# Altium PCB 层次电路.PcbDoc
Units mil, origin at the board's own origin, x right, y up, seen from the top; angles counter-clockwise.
Board outline 3000 x 3000 mil, 4 copper layers (Top Layer, VCC, GND, Bottom Layer), stack 30.634 mil thick; 34 components, 49 nets, 170 pads, 0 vias.
Unrouted connection lines stored in the file: 119.
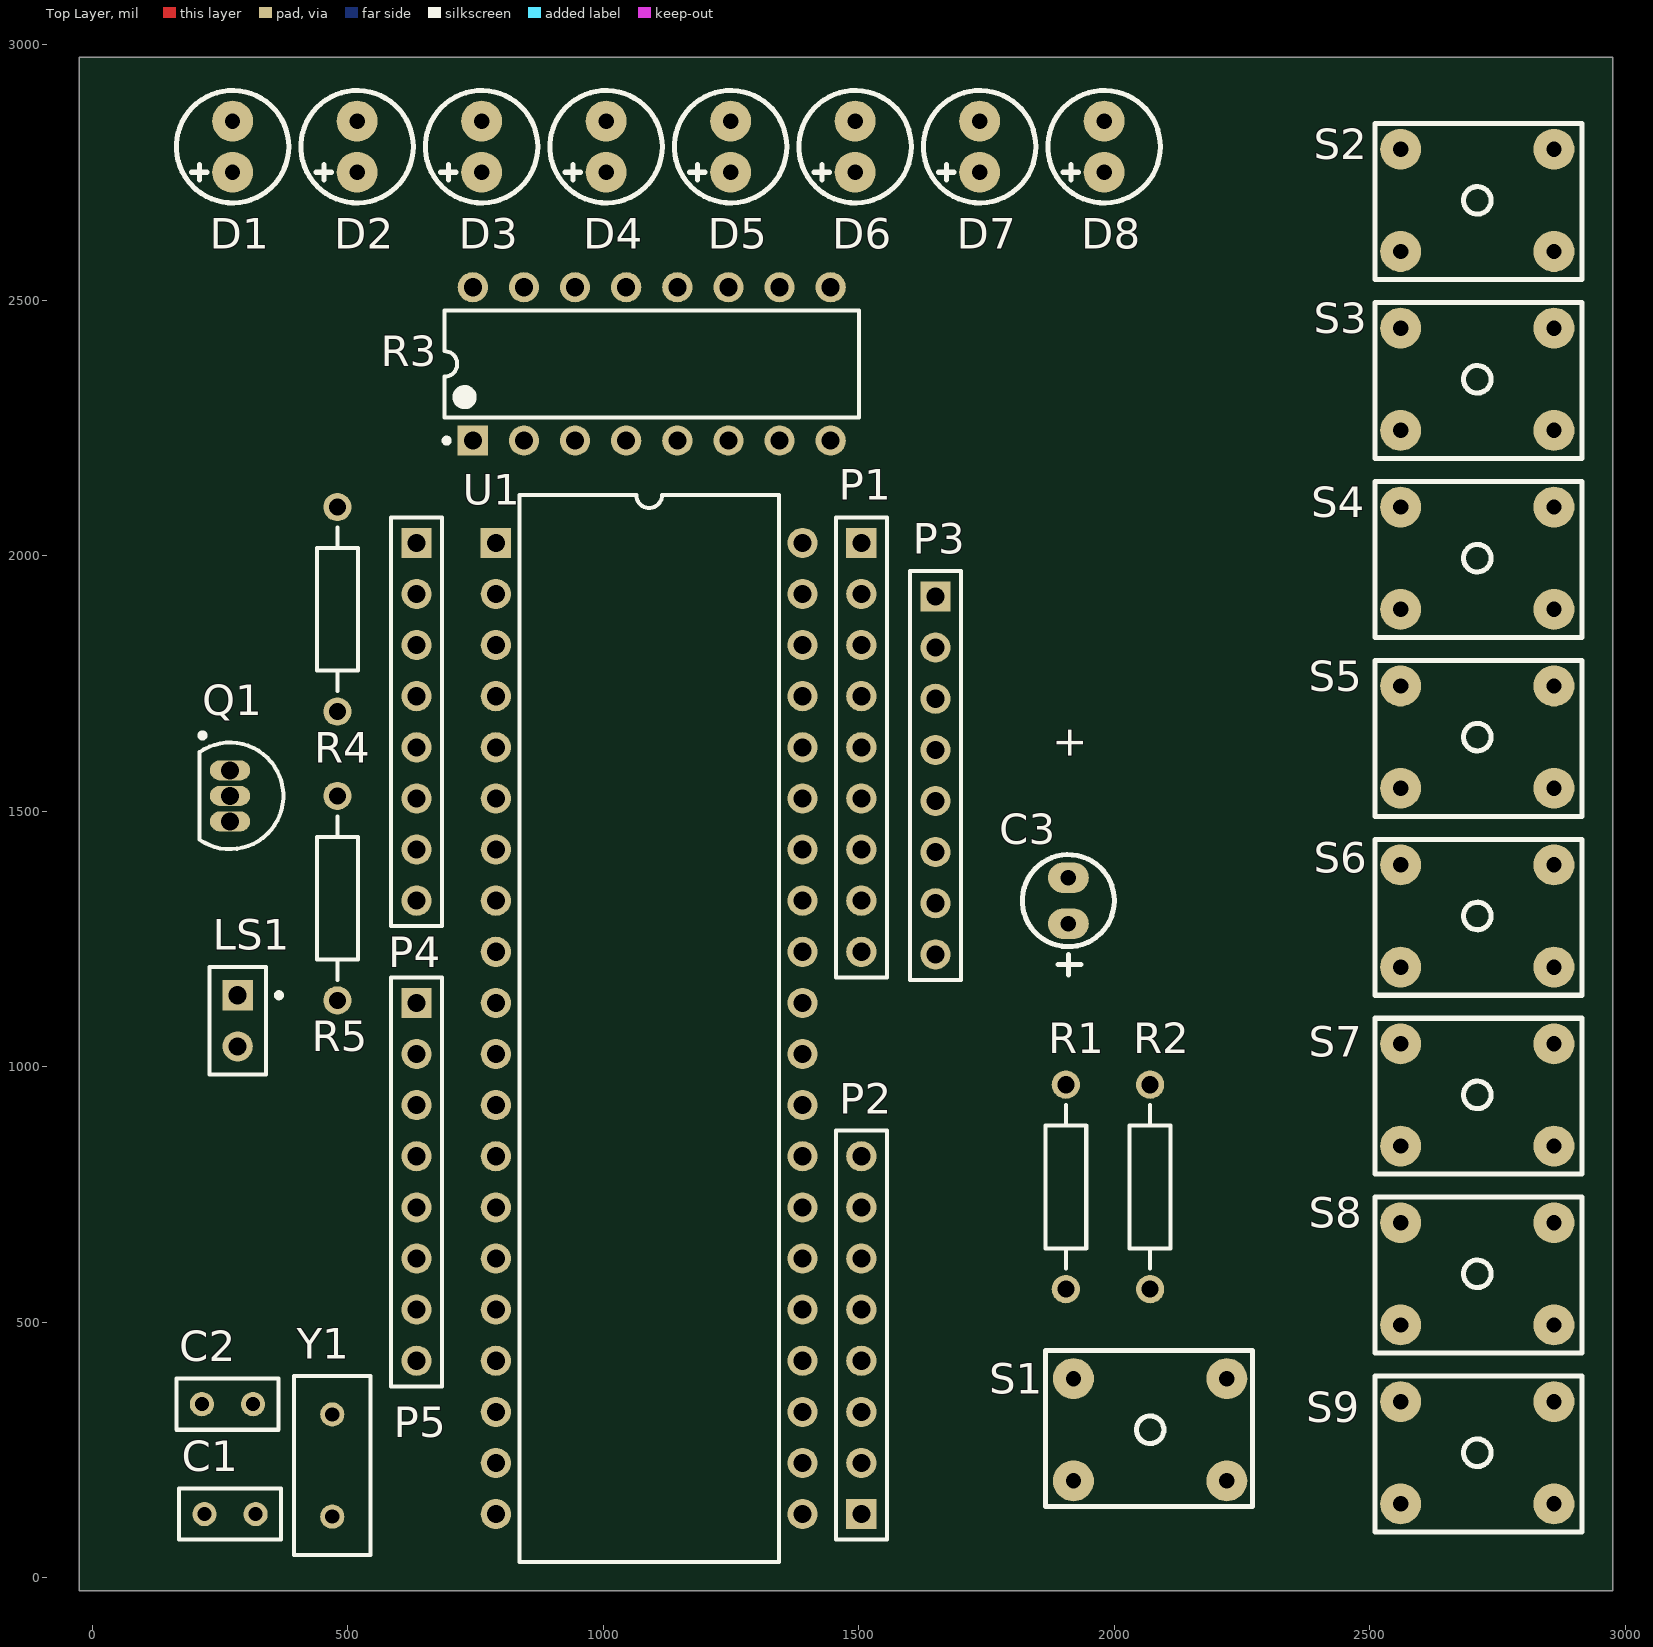
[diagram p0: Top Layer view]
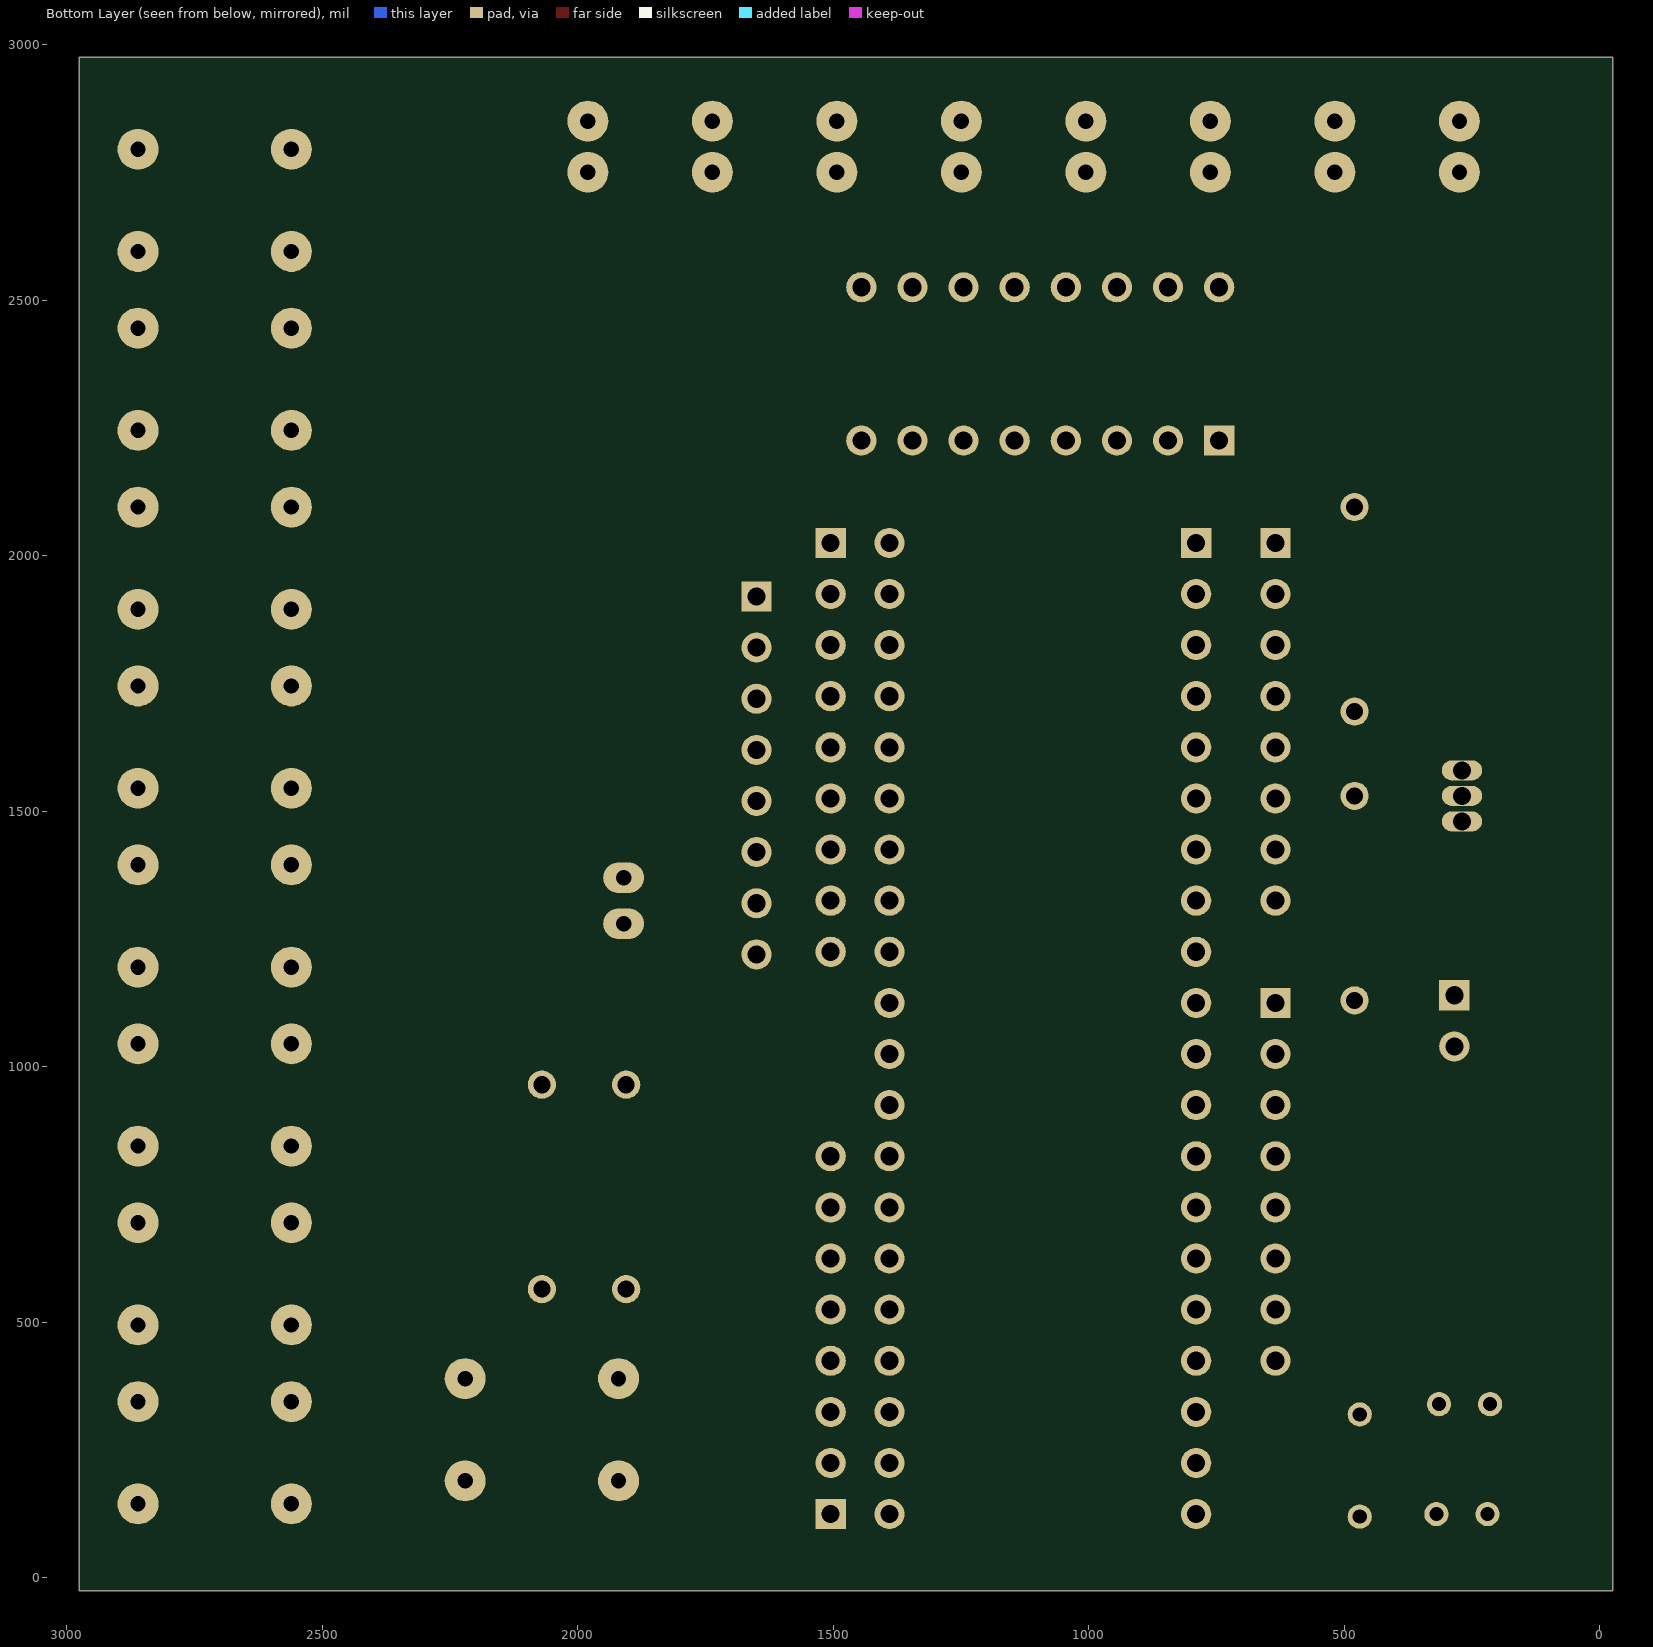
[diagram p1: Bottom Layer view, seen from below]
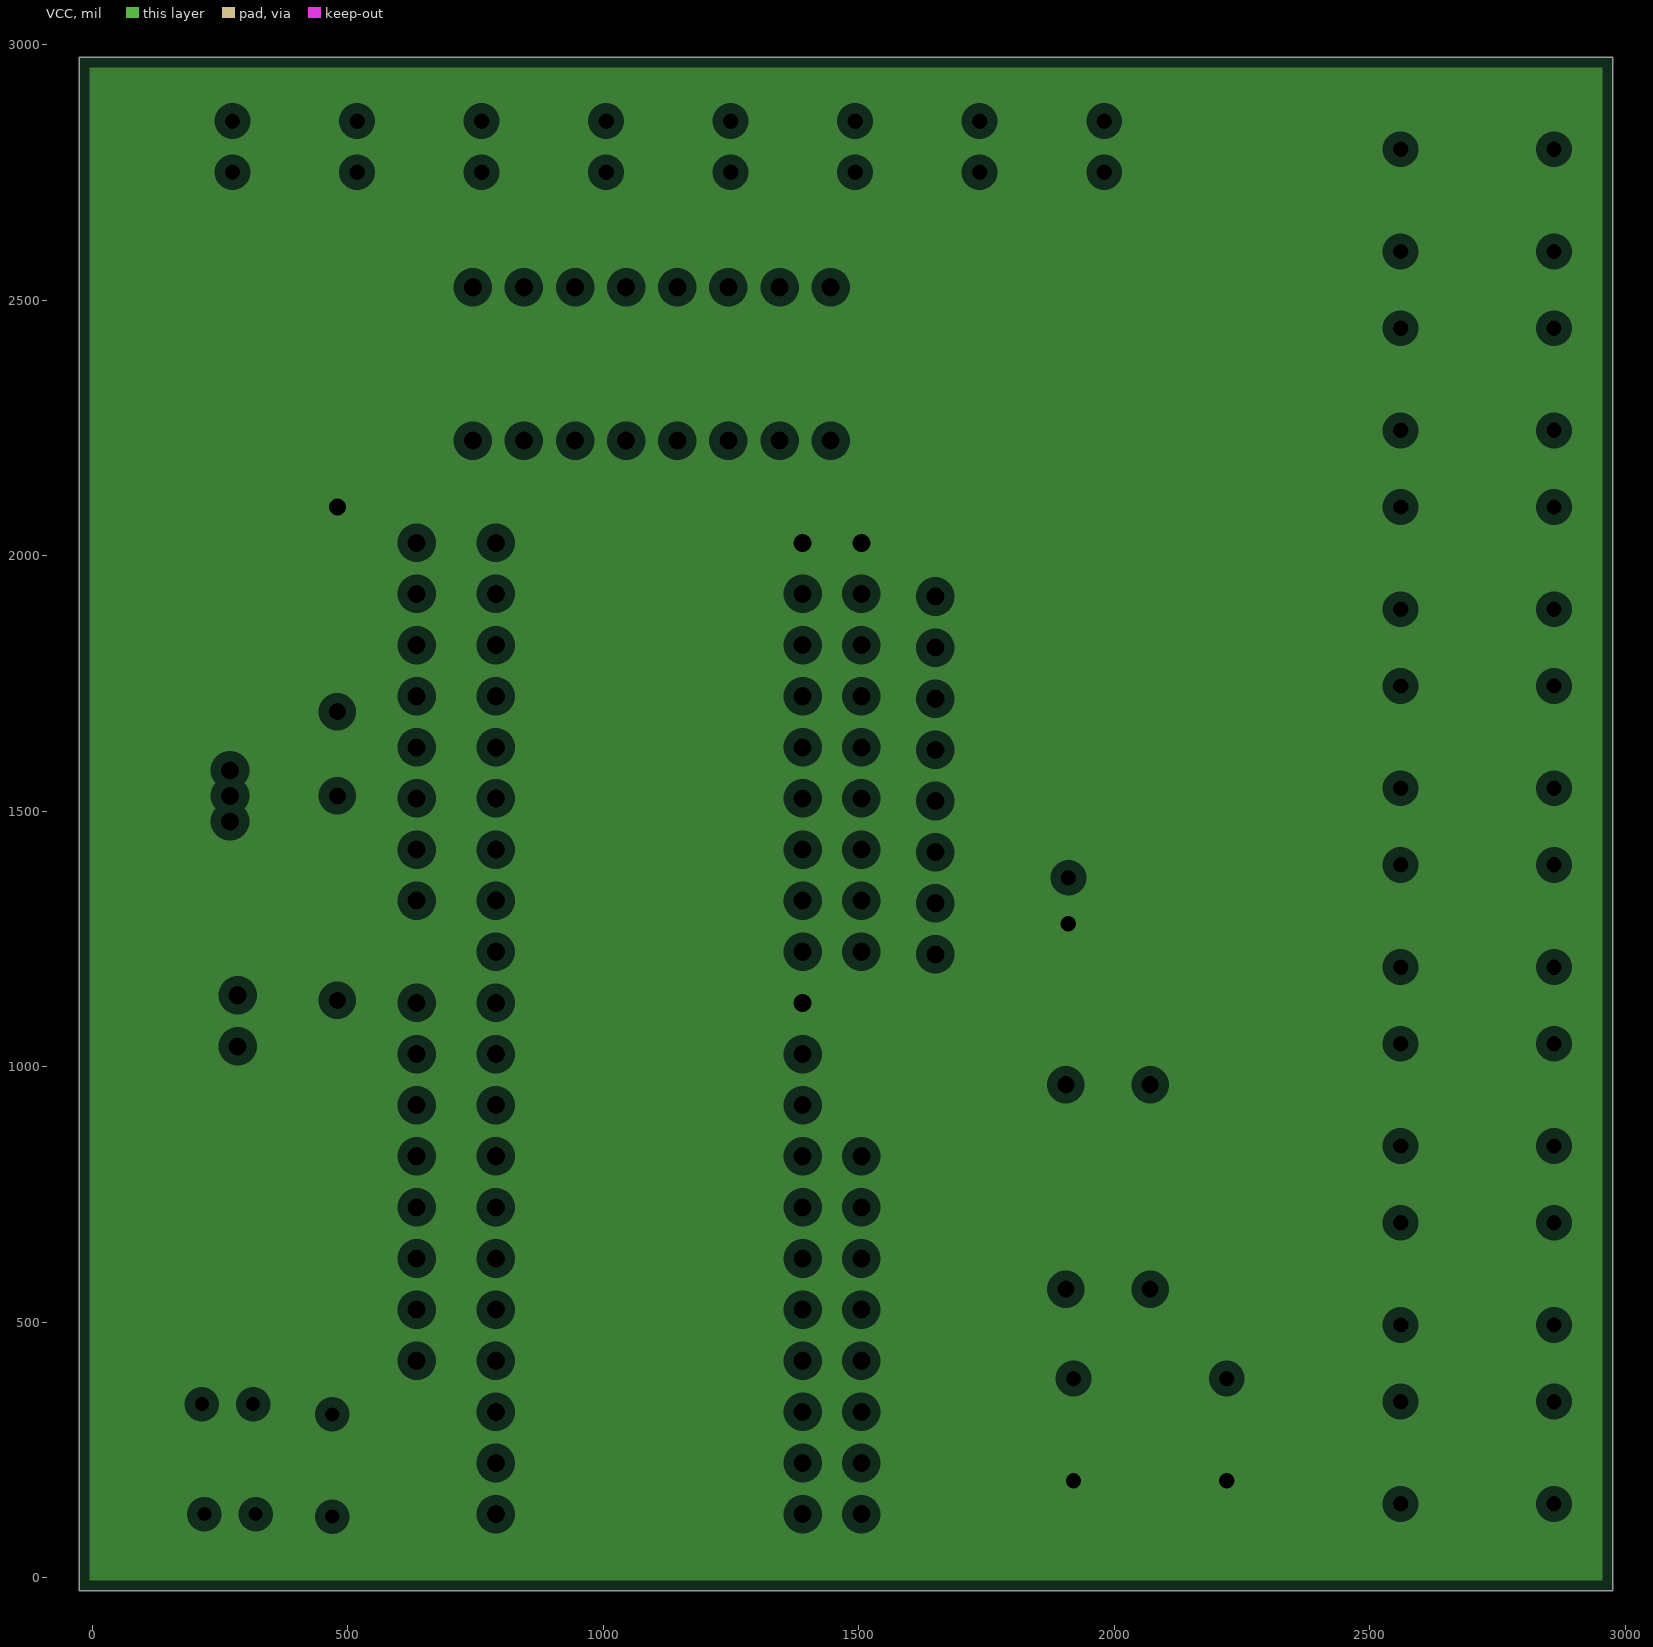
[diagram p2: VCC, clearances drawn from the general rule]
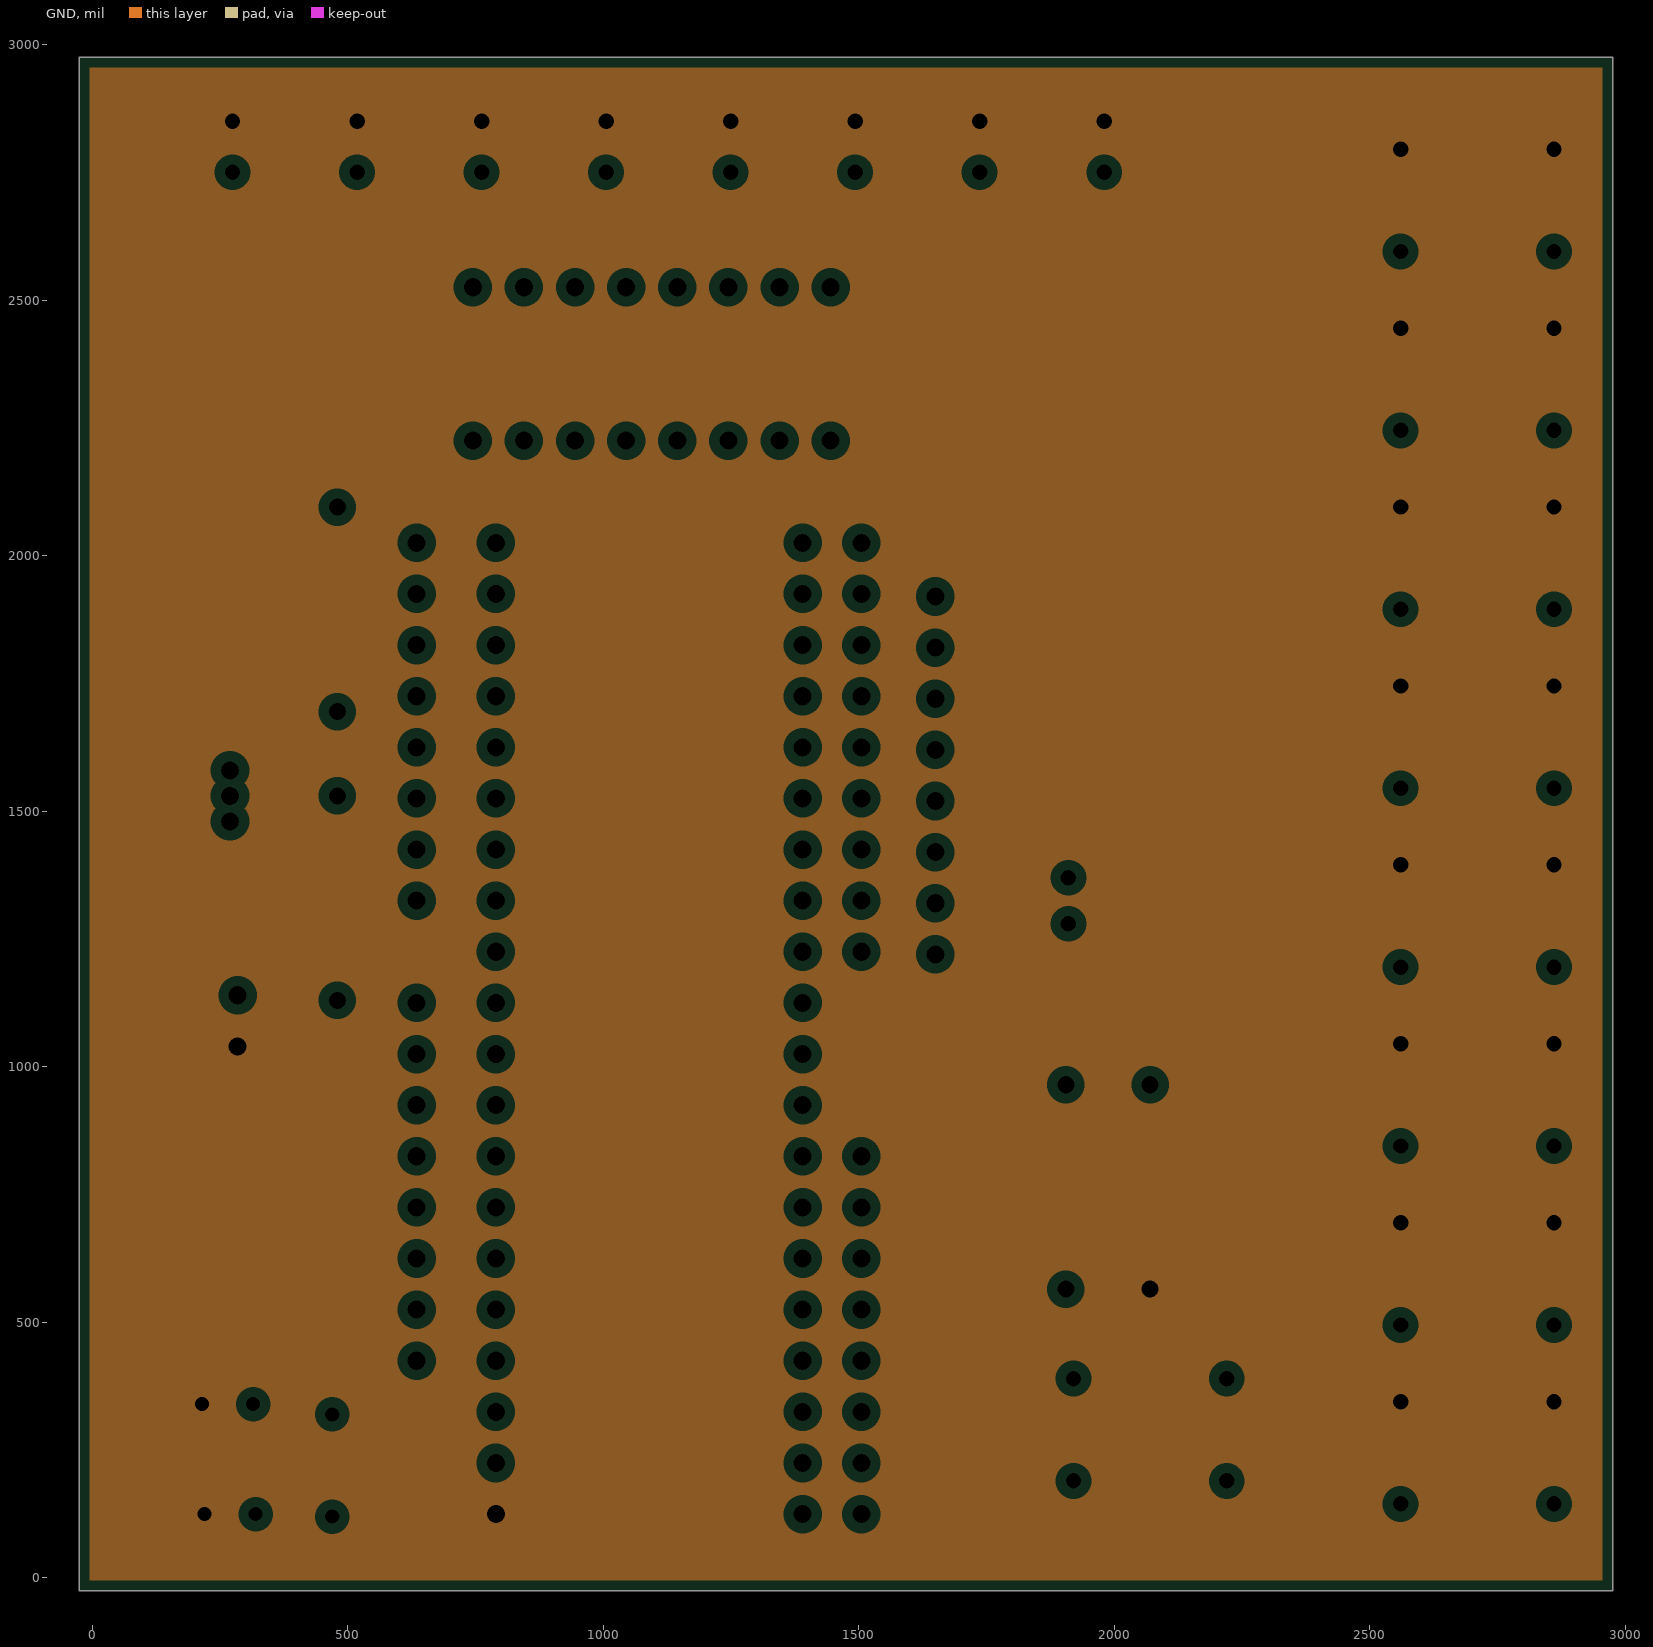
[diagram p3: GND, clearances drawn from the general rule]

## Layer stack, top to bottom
Top Solder: solder mask 0.4, Solder Resist, Dk 3.5
Top Layer: signal copper 1.4
Dielectric 1: core 10, FR-4, Dk 4.2
VCC: plane copper 1.417, net VCC
Dielectric 3: prepreg 5, Dk 4.2
GND: plane copper 1.417, net GND
Dielectric 2: core 10, Dk 4.2
Bottom Layer: signal copper 1.4
Bottom Solder: solder mask 0.4, Solder Resist, Dk 3.5

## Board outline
-25,-25 -25,2975 2975,2975 2975,-25

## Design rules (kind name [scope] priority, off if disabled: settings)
Clearance [All] p1: gap=10
PlaneClearance [All] p1: clearance=20
PlaneConnect [All] p1: planeconnectstyle=Relief reliefexpansion=20 reliefentries=4 reliefconductorwidth=10 reliefairgap=10
PolygonConnect [All] p1: connectstyle=Relief reliefconductorwidth=10 reliefentries=4 polygonreliefangle="90 Angle" airgapwidth=10
RoutingVias [All] p1: holewidth=28 width=50 viastyle="Through Hole" minholewidth=28 minwidth=50 maxholewidth=28 maxwidth=50
SolderMaskExpansion [All] p1: expansion=4
Width [All] p1: maxlimit=10 minlimit=10 preferedwidth=10
28 further rules are at their usual default settings.

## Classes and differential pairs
component class U_输出模块: D1 D2 D3 D4 D5 D6 D7 D8 LS1 Q1 R3 R4 R5
component class U_输入模块: S2 S3 S4 S5 S6 S7 S8 S9
component class U_复位、晶振模块: C1 C2 C3 R1 R2 S1 Y1
component class U_CPU模块: P1 P2 P3 P4 P5 U1

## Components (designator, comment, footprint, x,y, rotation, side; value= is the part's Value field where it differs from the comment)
C1 "Cap" RAD-0.1 270,125 r0 top
C2 "Cap" RAD-0.1 265,340 r0 top
C3 "Cap Pol1" 电解电容47UF 1910,1280 r90 top
D1 "LED0" 发光二极管 275,2750 r90 top
D2 "LED0" 发光二极管 518.57,2750 r90 top
D3 "LED0" 发光二极管 762.14,2750 r90 top
D4 "LED0" 发光二极管 1005.71,2750 r90 top
D5 "LED0" 发光二极管 1249.29,2750 r90 top
D6 "LED0" 发光二极管 1492.86,2750 r90 top
D7 "LED0" 发光二极管 1736.43,2750 r90 top
D8 "LED0" 发光二极管 1980,2750 r90 top
LS1 "Speaker" PIN2 285,1140 r270 top
P1 "1K" HDR1X9 1505,2025 r270 top
P2 "Header 8" HDR1X8 1505,125 r90 top
P3 "Header 8" HDR1X8 1650,1920 r270 top
P4 "Header 8" HDR1X8 635,2025 r270 top
P5 "Header 8" HDR1X8 635,1125 r270 top
Q1 "NPN" TO-226-AA 270,1530 r180 top
R1 "Res2" AXIAL-0.4 1905,765 r270 top
R2 "Res2" AXIAL-0.4 2070,765 r90 top
R3 "Res Pack4" DIP-16 1095,2375 r90 top
R4 "Res2" AXIAL-0.4 480,1895 r90 top
R5 "Res2" AXIAL-0.4 480,1330 r90 top
S1 "SW-PB" 轻触开关 1920,390 r0 top
S2 "SW-PB" 轻触开关 2860,2595 r180 top
S3 "SW-PB" 轻触开关 2860,2245 r180 top
S4 "SW-PB" 轻触开关 2860,1895 r180 top
S5 "SW-PB" 轻触开关 2860,1545 r180 top
S6 "SW-PB" 轻触开关 2860,1195 r180 top
S7 "SW-PB" 轻触开关 2860,845 r180 top
S8 "SW-PB" 轻触开关 2860,495 r180 top
S9 "SW-PB" 轻触开关 2860,145 r180 top
U1 "P89C52X2BN" DIP40 1090,1075 r270 top
Y1 "XTAL" RAD-0.2 470,220 r90 top

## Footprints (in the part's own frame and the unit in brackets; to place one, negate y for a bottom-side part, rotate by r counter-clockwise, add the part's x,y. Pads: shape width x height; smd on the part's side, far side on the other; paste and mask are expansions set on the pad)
AXIAL-0.4 [mm] "Axial Device, Thru-Hole; 2 Leads; 0.4 in Pin Spacing"
  round 1.4 hole 0.85: 1(-5.08,0) 2(5.08,0)
  silkscreen extent -4.06,-1.02 4.06,1.02
DIP40 [mm] "DIP; 40 Leads; Row Spacing 15.24 mm; Pitch 2.54 mm"
  rect 1.5x1.5 hole 0.9: 1(-24.13,-7.62)
  round 1.5 hole 0.9: 2(-21.59,-7.62) 3(-19.05,-7.62) 4(-16.51,-7.62) 5(-13.97,-7.62) 6(-11.43,-7.62) 7(-8.89,-7.62) 8(-6.35,-7.62) 9(-3.81,-7.62) 10(-1.27,-7.62) 11(1.27,-7.62) 12(3.81,-7.62) 13(6.35,-7.62) 14(8.89,-7.62) 15(11.43,-7.62) 16(13.97,-7.62) 17(16.51,-7.62) 18(19.05,-7.62) 19(21.59,-7.62) 20(24.13,-7.62) 21(24.13,7.62) 22(21.59,7.62) 23(19.05,7.62) 24(16.51,7.62) 25(13.97,7.62) 26(11.43,7.62) 27(8.89,7.62) 28(6.35,7.62) 29(3.81,7.62) 30(1.27,7.62) 31(-1.27,7.62) 32(-3.81,7.62) 33(-6.35,7.62) 34(-8.89,7.62) 35(-11.43,7.62) 36(-13.97,7.62) 37(-16.51,7.62) 38(-19.05,7.62) 39(-21.59,7.62) 40(-24.13,7.62)
  silkscreen extent -26.5,-6.45 26.5,6.45
DIP-16 [mm] "DIP; 16 Leads; Row Spacing 7.62 mm; Pitch 2.54 mm"
  rect 1.5x1.5 hole 0.9: 1(-3.81,8.89)
  round 1.5 hole 0.9: 2(-3.81,6.35) 3(-3.81,3.81) 4(-3.81,1.27) 5(-3.81,-1.27) 6(-3.81,-3.81) 7(-3.81,-6.35) 8(-3.81,-8.89) 9(3.81,-8.89) 10(3.81,-6.35) 11(3.81,-3.81) 12(3.81,-1.27) 13(3.81,1.27) 14(3.81,3.81) 15(3.81,6.35) 16(3.81,8.89)
  silkscreen extent -3.93,-10.3 2.65,10.31, body extent -3.6,-10.28 3.6,10.28, height 5.08
HDR1X8 [mm] "Connector; Header; 8 Position"
  rect 1.5x1.5 hole 0.9: 1(0,0)
  round 1.5 hole 0.9: 2(2.54,0) 3(5.08,0) 4(7.62,0) 5(10.16,0) 6(12.7,0) 7(15.24,0) 8(17.78,0)
  silkscreen extent -1.27,-1.27 19.05,1.27
HDR1X9 [mm] "Connector; Header; 9 Position"
  rect 1.5x1.5 hole 0.9: 1(0,0)
  round 1.5 hole 0.9: 2(2.54,0) 3(5.08,0) 4(7.62,0) 5(10.16,0) 6(12.7,0) 7(15.24,0) 8(17.78,0) 9(20.32,0)
  silkscreen extent -1.27,-1.27 21.59,1.27
PIN2 [mm] "Photosensitive Diode; 2 Leads"
  rect 1.5x1.5 hole 0.9: 1(0,0)
  round 1.5 hole 0.9: 2(2.54,0)
  silkscreen extent -1.4,-1.4 3.94,2.18
RAD-0.1 [mm] "Radial Cap, Thru-Hole; 2 Leads; 0.1 in Pin Spacing"
  round 1.2 hole 0.7: 1(-1.27,0) 2(1.27,0)
  silkscreen extent -2.54,-1.27 2.54,1.27
RAD-0.2 [mm] "Radial Cap, Thru-Hole; 2 Leads; 0.2 in Pin Spacing"
  round 1.2 hole 0.7: 1(-2.54,0) 2(2.54,0)
  silkscreen extent -4.45,-1.91 4.45,1.91
TO-226-AA [mm] "TO, Flat Index; 3 In-Line, Axial Leads; Body Dia. 4.8mm; Leads 0.55 x 0.51 mm (max)"
  oval 2x1 hole 0.9: 1(0,-1.27) 2(0,0) 3(0,1.27)
  silkscreen extent -2.65,-3.13 1.52,2.65, body extent -2.65,-2.66 1.52,2.66, height 5.33
发光二极管 [mil]
  round 80 hole 30: 1(0,0) 2(100,0)
  silkscreen extent -60,-110 160,110
电解电容47UF [mil]
  oval 60x80 hole 30: 1(0,0) 2(90,0)
  silkscreen extent -100,-90 135,90
轻触开关 [mil]
  round 80 hole 30: 1(0,0) 1(300,0) 2(0,-200) 2(300,-200)
  silkscreen extent -55,-250 350,55

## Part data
C1 C2: "Capacitor"
C3: "Polarized Capacitor (Radial)"
D1 D2 D3 D4 D5 D6 D7 D8: "Typical INFRARED GaAs LED"
LS1: "Loudspeaker"
P1: library part "Header 9", "Header, 9-Pin"
P2 P3 P4 P5: "Header, 8-Pin"
Q1: "NPN Bipolar Transistor"
R1 R2 R4 R5: "Resistor"
R3: "Isolated Resistor Network"
S1 S2 S3 S4 S5 S6 S7 S8 S9: "Switch"
U1: "80C51 8-Bit Flash Microcontroller Family, 8 kB Flash"
Y1: "Crystal Oscillator"

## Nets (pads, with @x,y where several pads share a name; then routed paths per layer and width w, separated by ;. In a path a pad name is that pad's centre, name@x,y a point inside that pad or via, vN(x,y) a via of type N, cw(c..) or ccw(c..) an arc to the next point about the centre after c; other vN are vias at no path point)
A: D1.1 R3.16
A0: P1.2 P3.1 S2.1 U1.39
A1: P1.3 P3.2 S3.1 U1.38
A2: P1.4 P3.3 S4.1 U1.37
A3: P1.5 P3.4 S5.1 U1.36
A4: P1.6 P3.5 S6.1 U1.35
A5: P1.7 P3.6 S7.1 U1.34
A6: P1.8 P3.7 S8.1 U1.33
A7: P1.9 P3.8 S9.1 U1.32
B: D2.1 R3.15
C: D3.1 R3.14
D: D4.1 R3.13
D0: P4.1 R3.1 U1.1
D1: P4.2 R3.2 U1.2
D2: P4.3 R3.3 U1.3
D3: P4.4 R3.4 U1.4
D4: P4.5 R3.5 U1.5
D5: P4.6 R3.6 U1.6
D6: P4.7 R3.7 U1.7
D7: P4.8 R3.8 U1.8
D8: P2.1 U1.21
D9: P2.2 U1.22
D10: P2.3 U1.23
D11: P2.4 U1.24
D12: P2.5 U1.25
D13: P2.6 U1.26
D14: P2.7 U1.27
D15: P2.8 U1.28
E: D5.1 R3.12
F: D6.1 R3.11
G: D7.1 R3.10
GND: C1.1 C2.1 D1.2 D2.2 D3.2 D4.2 D5.2 D6.2 D7.2 D8.2 LS1.2 R2.1 S2.2 S3.2 S4.2 S5.2 S6.2 S7.2 S8.2 S9.2 U1.20
H: D8.1 R3.9
NetC1_2: C1.2 U1.19 Y1.1
NetC2_2: C2.2 U1.18 Y1.2
NetC3_2: C3.2 R1.1 R2.2 U1.9
NetLS1_1: LS1.1 Q1.3
NetQ1_1: Q1.1 R4.1
NetQ1_2: Q1.2 R5.2
NetR1_2: R1.2 S1.1
P30: P5.1 R5.1 U1.10
P31: P5.2 U1.11
P32: P5.3 U1.12
P33: P5.4 U1.13
P34: P5.5 U1.14
P35: P5.6 U1.15
P36: P5.7 U1.16
P37: P5.8 U1.17
VCC: C3.1 P1.1 R4.2 S1.2 U1.31 U1.40
pads on no net: U1.29 U1.30

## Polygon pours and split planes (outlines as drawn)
GND on GND (split plane): 2954.9,-4.9 -4.9,-4.9 -4.9,2954.9 2954.9,2954.9
VCC on VCC (split plane): 2954.9,-4.9 -4.9,-4.9 -4.9,2954.9 2954.9,2954.9

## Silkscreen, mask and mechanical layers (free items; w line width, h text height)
Mechanical 1:
  lines w10: -25,-25 2975,-25 2975,2975 -25,2975 -25,-25 ; 0,0 0,2950 2950,2950 2950,0 0,0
